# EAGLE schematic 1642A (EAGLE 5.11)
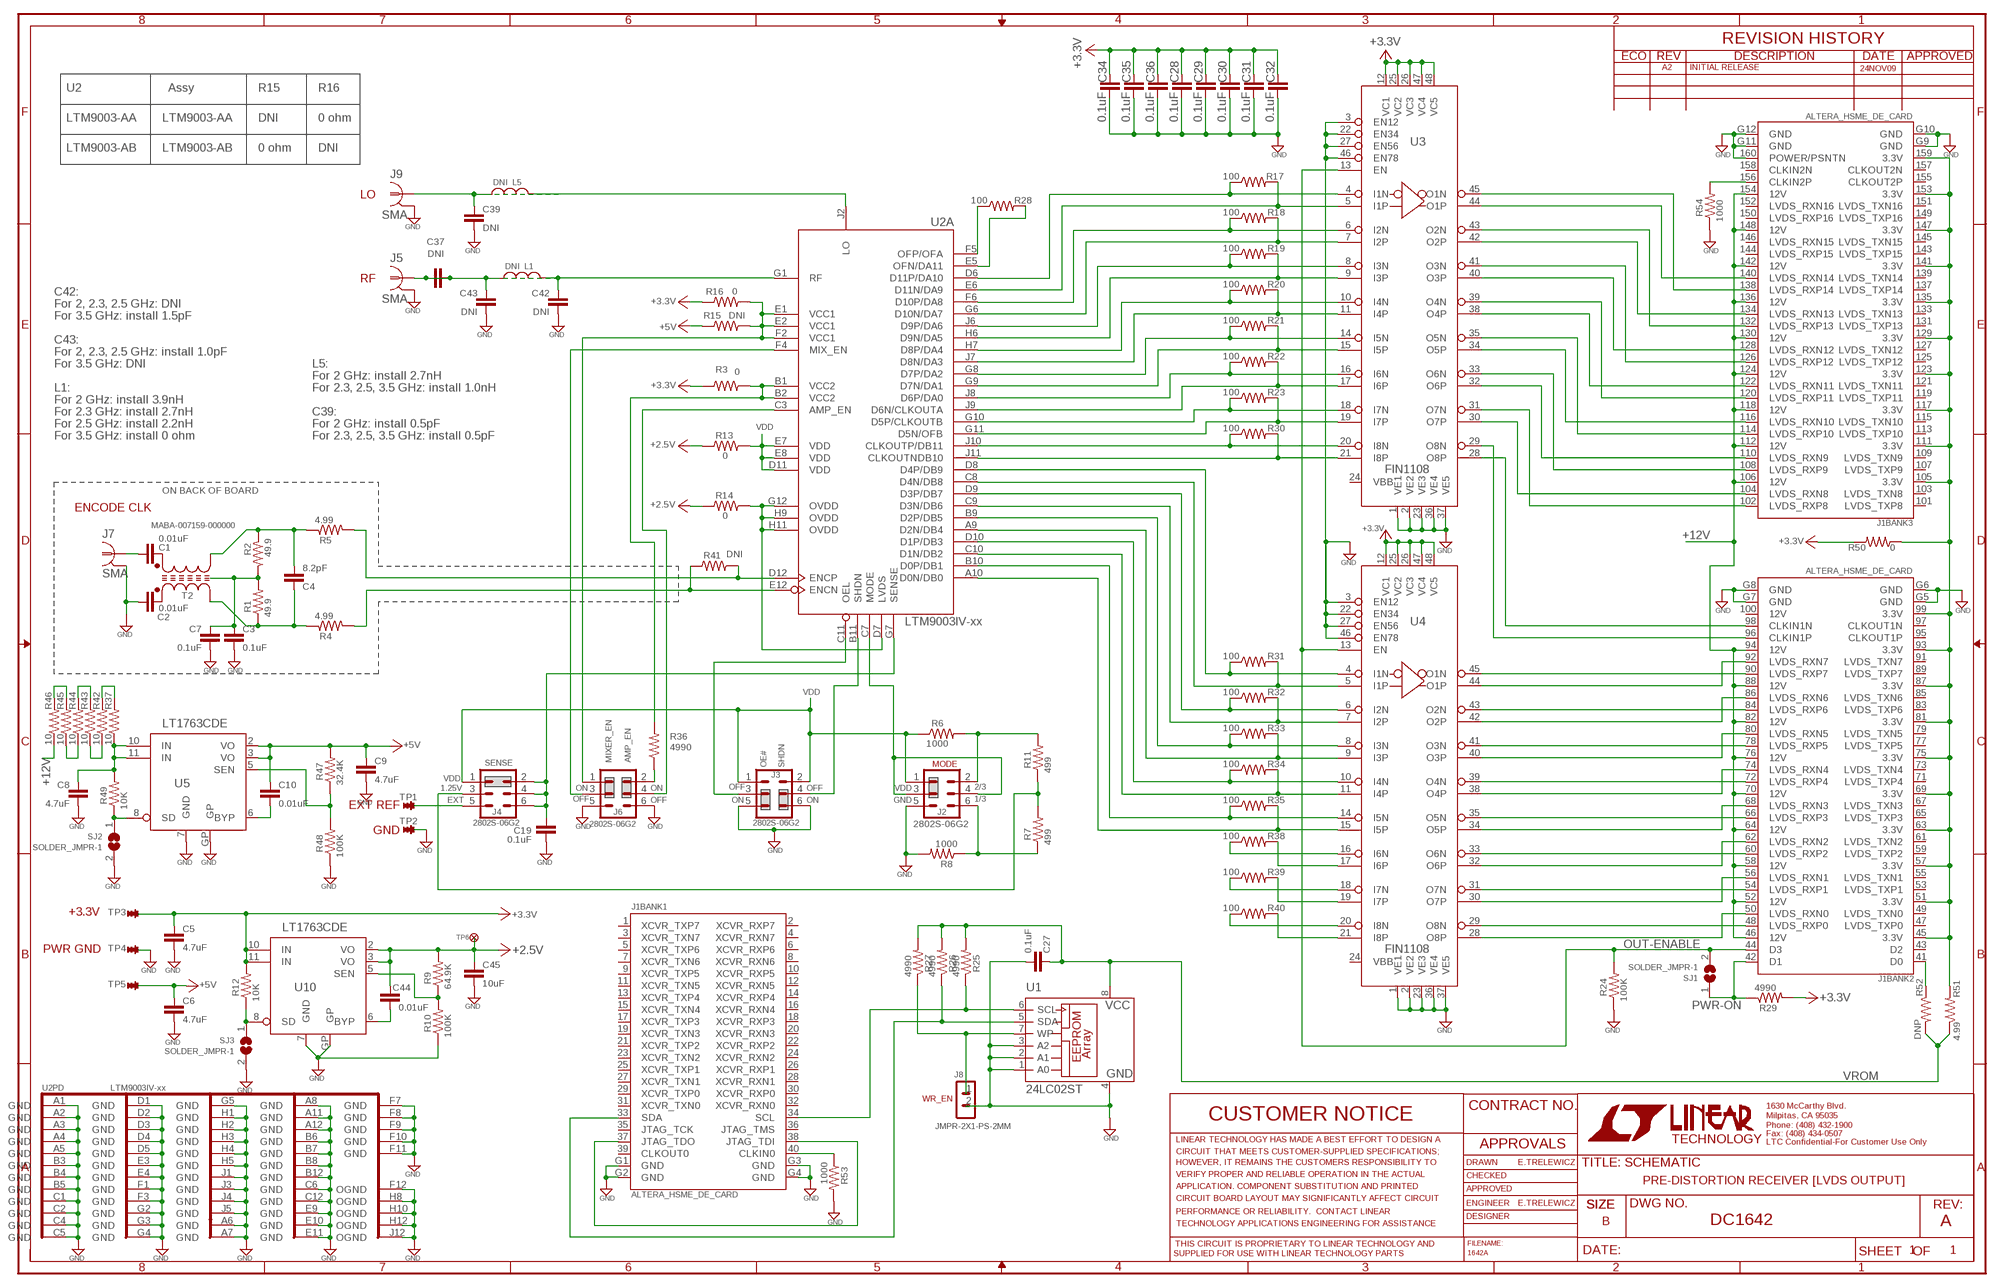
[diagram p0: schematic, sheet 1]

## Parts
C1  0.01uF  CAP-NP-SMT-C0402  [C0402]
C2  0.01uF  CAP-NP-SMT-C0402  [C0402]
C3  0.1uF  CAP-NP-SMT-C0603  [C0603]
C4  8.2pF  CAP-NP-SMT-C0402  [C0402]
C5  4.7uF  CAP-NP-SMT-C0805  [C0805]
C6  4.7uF  CAP-NP-SMT-C0805  [C0805]
C7  0.1uF  CAP-NP-SMT-C0603  [C0603]
C8  4.7uF  CAP-NP-SMT-C0805  [C0805]
C9  4.7uF  CAP-NP-SMT-C0805  [C0805]
C10  0.01uF  CAP-NP-SMT-C0402  [C0402]
C19  0.1uF  CAP-NP-SMT-C0402  [C0402]
C27  0.1uF  CAP-NP-SMT-C0402  [C0402]
C28  0.1uF  CAP-NP-SMT-C0402  [C0402]
C29  0.1uF  CAP-NP-SMT-C0402  [C0402]
C30  0.1uF  CAP-NP-SMT-C0402  [C0402]
C31  0.1uF  CAP-NP-SMT-C0402  [C0402]
C32  0.1uF  CAP-NP-SMT-C0402  [C0402]
C34  0.1uF  CAP-NP-SMT-C0402  [C0402]
C35  0.1uF  CAP-NP-SMT-C0402  [C0402]
C36  0.1uF  CAP-NP-SMT-C0402  [C0402]
C37  DNI  CAP-NP-SMT-C0402  [C0402]
C39  DNI  CAP-NP-SMT-C0402  [C0402]
C42  DNI  CAP-NP-SMT-C0402  [C0402]
C43  DNI  CAP-NP-SMT-C0402  [C0402]
C44  0.01uF  CAP-NP-SMT-C0402  [C0402]
C45  10uF  CAP-NP-SMT-C0805  [C0805]
J1  ALTERA_HSME_DE_CARD  [HSMC_ASP-122952-01_MEZZANINECARD]
J2  2802S-06G2  HDR-3X2-PS2MM  [HDR-3X2PS-2MM]
J3  2802S-06G2  HDR-3X2-PS2MM  [HDR-3X2PS-2MM]
J4  2802S-06G2  HDR-3X2-PS2MM  [HDR-3X2PS-2MM]
J5  SMA  RF_CONN-SMA-FEMALE-EDGE-MNT-GHZ  [SMA_FEMALE_EDGE_MNT_GHZ]
J6  2802S-06G2  HDR-3X2-PS2MM  [HDR-3X2PS-2MM]
J7  SMA  RF_CONN-SMA-FEMALE-EDGE-MNT  [SMA-FEMALE-EDGE-MNT]
J8  JMPR-2X1-PS-2MM  [HDR-2X1PS-2MM]
J9  SMA  RF_CONN-SMA-FEMALE-EDGE-MNT-GHZ  [SMA_FEMALE_EDGE_MNT_GHZ]
L1  DNI  IND-CER-SMT-0402  [L0402]
L5  DNI  IND-CER-SMT-0402  [L0402]
R1  49.9  RES-R0402  [R0402]
R2  49.9  RES-R0402  [R0402]
R3  0  RES-R0805  [R0805]
R4  4.99  RES-R0402  [R0402]
R5  4.99  RES-R0402  [R0402]
R6  1000  RES-R0603  [R0603]
R7  499  RES-R0603  [R0603]
R8  1000  RES-R0603  [R0603]
R9  64.9K  RES-R0402  [R0402]
R10  100K  RES-R0402  [R0402]
R11  499  RES-R0603  [R0603]
R12  10K  RES-R0402  [R0402]
R13  0  RES-R0805  [R0805]
R14  0  RES-R0805  [R0805]
R15  DNI  RES-R0805  [R0805]
R16  0  RES-R0805  [R0805]
R17  100  RES-R0201  [R0201]
R18  100  RES-R0201  [R0201]
R19  100  RES-R0201  [R0201]
R20  100  RES-R0201  [R0201]
R21  100  RES-R0201  [R0201]
R22  100  RES-R0201  [R0201]
R23  100  RES-R0201  [R0201]
R24  100K  RES-R0402  [R0402]
R25  4990  RES-R0402  [R0402]
R26  4990  RES-R0402  [R0402]
R27  4990  RES-R0402  [R0402]
R28  100  RES-R0201  [R0201]
R29  4990  RES-R0402  [R0402]
R30  100  RES-R0201  [R0201]
R31  100  RES-R0201  [R0201]
R32  100  RES-R0201  [R0201]
R33  100  RES-R0201  [R0201]
R34  100  RES-R0201  [R0201]
R35  100  RES-R0201  [R0201]
R36  4990  RES-R0402  [R0402]
R37  10  RES-R1206  [R1206]
R38  100  RES-R0201  [R0201]
R39  100  RES-R0201  [R0201]
R40  100  RES-R0201  [R0201]
R41  DNI  RES-R0201  [R0201]
R42  10  RES-R1206  [R1206]
R43  10  RES-R1206  [R1206]
R44  10  RES-R1206  [R1206]
R45  10  RES-R1206  [R1206]
R46  10  RES-R1206  [R1206]
R47  32.4K  RES-R0402  [R0402]
R48  100K  RES-R0402  [R0402]
R49  10K  RES-R0402  [R0402]
R50  0  RES-R1206  [R1206]
R51  4.99  RES-R0402  [R0402]
R52  DNP  RES-R0402  [R0402]
R53  1000  RES-R0603  [R0603]
R54  1000  RES-R0603  [R0603]
SJ1  SOLDER_JMPR-1  [SJ1]
SJ2  SOLDER_JMPR-1  [SJ1]
SJ3  SOLDER_JMPR-1  [SJ1]
T2  MABA-007159-000000  ETC1-1-13  [MACOM_ETC1-XFMR]
TP1  TURRET0.063  [TURRET_MILLMAX_2308-2]
TP2  TURRET0.063  [TURRET_MILLMAX_2308-2]
TP3  TURRET0.063  [TURRET_MILLMAX_2308-2]
TP4  TURRET0.063  [TURRET_MILLMAX_2308-2]
TP5  TURRET0.063  [TURRET_MILLMAX_2308-2]
TP6  TSTPNT25MIL  [VIA-25MIL]
U1  24LC02ST  [TSSOP8]
U2  LTM9003IV-xx  LTM9003  [LTM9003-RNDED]
U3  FIN1108  [TSSOP48]
U4  FIN1108  [TSSOP48]
U5  LT1763CDE  [DE12]
U10  LT1763CDE  [DE12]

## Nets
3.3VHOST: J1.45(BANK2:3.3V) J1.51(BANK2:3.3V) J1.57(BANK2:3.3V) J1.63(BANK2:3.3V) J1.69(BANK2:3.3V) J1.75(BANK2:3.3V) J1.81(BANK2:3.3V) J1.87(BANK2:3.3V) J1.93(BANK2:3.3V) J1.99(BANK2:3.3V) J1.105(BANK3:3.3V) J1.111(BANK3:3.3V) J1.117(BANK3:3.3V) J1.123(BANK3:3.3V) J1.129(BANK3:3.3V) J1.135(BANK3:3.3V) J1.141(BANK3:3.3V) J1.147(BANK3:3.3V) J1.153(BANK3:3.3V) J1.159(BANK3:3.3V) R50.1 R51.2
+2.5V: C44.1 C45.1 R9.2 R13.1 R14.1 TP6.1 U10.2(VO) U10.3(VO)
+3.3V: C5.1 C28.1 C29.1 C30.1 C31.1 C32.1 C34.1 C35.1 C36.1 R3.1 R12.2 R16.1 R29.2 R50.2 TP3.1 U3.12(VC1) U3.25(VC2) U3.26(VC3) U3.47(VC4) U3.48(VC5) U4.12(VC1) U4.25(VC2) U4.26(VC3) U4.47(VC4) U4.48(VC5) U10.10(IN) U10.11(IN)
+5V: C6.1 C9.1 C10.1 R15.1 R47.2 TP5.1 U5.2(VO) U5.3(VO)
+12V: J1.46(BANK2:12V) J1.52(BANK2:12V) J1.58(BANK2:12V) J1.64(BANK2:12V) J1.70(BANK2:12V) J1.76(BANK2:12V) J1.82(BANK2:12V) J1.88(BANK2:12V) J1.94(BANK2:12V) J1.106(BANK3:12V) J1.112(BANK3:12V) J1.118(BANK3:12V) J1.124(BANK3:12V) J1.130(BANK3:12V) J1.136(BANK3:12V) J1.142(BANK3:12V) J1.148(BANK3:12V) J1.154(BANK3:12V) R46.1
AMP_EN: J6.4 U2.C3(A:AMP_EN)
ECCN: R4.2 R41.1 U2.E12(A:ENCN)
ENCP: R5.2 R41.2 U2.D12(A:ENCP)
EXT_REF: J4.5 TP1.1
GND: C2.1 C3.2 C5.2 C6.2 C7.2 C8.2 C9.2 C19.2 C27.2 C28.2 C29.2 C30.2 C31.2 C32.2 C34.2 C35.2 C36.2 C39.2 C42.2 C43.2 C45.2 J1.160(BANK3:POWER/PSNTN) J1.G1(BANK1:GND) J1.G2(BANK1:GND) J1.G3(BANK1:GND) J1.G4(BANK1:GND) J1.G5(BANK2:GND) J1.G6(BANK2:GND) J1.G7(BANK2:GND) J1.G8(BANK2:GND) J1.G9(BANK3:GND) J1.G10(BANK3:GND) J1.G11(BANK3:GND) J1.G12(BANK3:GND) J2.5 J3.5 J3.6 J5.2(GND) J6.5 J6.6 J7.2(GND) J8.2 J9.2(GND) R8.2 R10.1 R24.1 R48.1 R53.2 R54.1 SJ2.2 SJ3.2 TP2.1 TP4.1 U1.1(A0) U1.2(A1) U1.3(A2) U1.4(GND) U2.A1(PD:GND) U2.A2(PD:GND) U2.A3(PD:GND) U2.A4(PD:GND) U2.A5(PD:GND) U2.A6(PD:GND) U2.A7(PD:GND) U2.A8(PD:GND) U2.A11(PD:GND) U2.A12(PD:GND) U2.B3(PD:GND) U2.B4(PD:GND) U2.B5(PD:GND) U2.B6(PD:GND) U2.B7(PD:GND) U2.B8(PD:GND) U2.B12(PD:GND) U2.C1(PD:GND) U2.C2(PD:GND) U2.C4(PD:GND) U2.C5(PD:GND) U2.C6(PD:GND) U2.C12(PD:GND) U2.D1(PD:GND) U2.D2(PD:GND) U2.D3(PD:GND) U2.D4(PD:GND) U2.D5(PD:GND) U2.E3(PD:GND) U2.E4(PD:GND) U2.E9(PD:GND) U2.E10(PD:GND) U2.E11(PD:GND) U2.F1(PD:GND) U2.F3(PD:GND) U2.F7(PD:GND) U2.F8(PD:GND) U2.F9(PD:GND) U2.F10(PD:GND) U2.F11(PD:GND) U2.F12(PD:OGND) U2.G2(PD:GND) U2.G3(PD:GND) U2.G4(PD:GND) U2.G5(PD:GND) U2.H1(PD:GND) U2.H2(PD:GND) U2.H3(PD:GND) U2.H4(PD:GND) U2.H5(PD:GND) U2.H8(PD:OGND) U2.H10(PD:OGND) U2.H12(PD:OGND) U2.J1(PD:GND) U2.J3(PD:GND) U2.J4(PD:GND) U2.J5(PD:GND) U2.J12(PD:OGND) U3.1(VE1) U3.2(VE2) U3.3(EN12) U3.22(EN34) U3.23(VE3) U3.27(EN56) U3.36(VE4) U3.37(VE5) U3.46(EN78) U4.1(VE1) U4.2(VE2) U4.3(EN12) U4.22(EN34) U4.23(VE3) U4.27(EN56) U4.36(VE4) U4.37(VE5) U4.46(EN78) U5.7(GND) U5.GP U10.7(GND) U10.GP
LO: L5.2 U2.J2(A:LO)
MIX_EN: J6.3 U2.F4(A:MIX_EN)
MODE: J2.3 J2.4 U2.C7(A:MODE)
N$1: C1.2 T2.4
N$2: C2.2 T2.5
N$3: C3.1 C7.1 R1.2 R2.2
N$4: C1.1 J7.1
N$5: R17.1 U2.D6(A:D11P/DA10) U3.4(I1N)
N$6: C4.2 R2.1 R5.1 T2.3
N$7: C4.1 R1.1 R4.1 T2.1
N$8: J6.2 R36.1
N$9: C37.1 C37.2 C43.1 J5.1 L1.1
N$10: R12.1 SJ3.1 U10.8(SD)
N$11: J2.6 R7.1 R8.1
N$12: R28.1 U2.F5(A:OFP/OFA)
N$13: C39.1 J9.1 L5.1
N$14: J1.48(BANK2:LVDS_RXP0) U4.29(O8N)
N$15: J2.2 R6.2 R11.2
N$16: J1.50(BANK2:LVDS_RXN0) U4.28(O8P)
N$17: J1.54(BANK2:LVDS_RXP1) U4.31(O7N)
N$18: J1.56(BANK2:LVDS_RXN1) U4.30(O7P)
N$19: J1.60(BANK2:LVDS_RXP2) U4.33(O6N)
N$20: J1.62(BANK2:LVDS_RXN2) U4.32(O6P)
N$21: J1.66(BANK2:LVDS_RXP3) U4.35(O5N)
N$22: J1.68(BANK2:LVDS_RXN3) U4.34(O5P)
N$23: J1.72(BANK2:LVDS_RXP4) U4.39(O4N)
N$24: J1.74(BANK2:LVDS_RXN4) U4.38(O4P)
N$25: J1.78(BANK2:LVDS_RXP5) U4.41(O3N)
N$26: J1.80(BANK2:LVDS_RXN5) U4.40(O3P)
N$27: J1.84(BANK2:LVDS_RXP6) U4.43(O2N)
N$28: J1.86(BANK2:LVDS_RXN6) U4.42(O2P)
N$29: J1.90(BANK2:LVDS_RXP7) U4.45(O1N)
N$30: R9.1 R10.2 U10.5(SEN)
N$31: J1.92(BANK2:LVDS_RXN7) U4.44(O1P)
N$32: J1.98(BANK2:CLKIN1N) U3.28(O8P)
N$33: J1.96(BANK2:CLKIN1P) U3.29(O8N)
N$34: J1.102(BANK3:LVDS_RXP8) U3.31(O7N)
N$35: J1.104(BANK3:LVDS_RXN8) U3.30(O7P)
N$36: C44.2 U10.6(BYP)
N$37: J1.108(BANK3:LVDS_RXP9) U3.33(O6N)
N$38: J1.110(BANK3:LVDS_RXN9) U3.32(O6P)
N$39: J1.114(BANK3:LVDS_RXP10) U3.35(O5N)
N$40: J1.116(BANK3:LVDS_RXN10) U3.34(O5P)
N$41: J1.120(BANK3:LVDS_RXP11) U3.39(O4N)
N$42: J1.122(BANK3:LVDS_RXN11) U3.38(O4P)
N$43: J1.126(BANK3:LVDS_RXP12) U3.41(O3N)
N$44: J1.128(BANK3:LVDS_RXN12) U3.40(O3P)
N$45: J1.132(BANK3:LVDS_RXP13) U3.43(O2N)
N$46: J1.134(BANK3:LVDS_RXN13) U3.42(O2P)
N$47: J1.41(BANK2:D0) R52.1
N$49: R28.2 U2.E5(A:OFN/DA11)
N$50: J1.138(BANK3:LVDS_RXP14) U3.45(O1N)
N$51: J1.140(BANK3:LVDS_RXN14) U3.44(O1P)
N$52: R49.1 SJ2.1 U5.8(SD)
N$53: R45.2 R46.2
N$54: R44.1 R45.1
N$55: R43.2 R44.2
N$56: J1.37(BANK1:JTAG_TDO) J1.38(BANK1:JTAG_TDI)
N$57: R42.1 R43.1
N$58: R37.2 R42.2
N$59: J1.40(BANK1:CLKIN0) R53.1
N$60: R30.2 U2.J11(A:CLKOUTNDB10) U3.21(I8P)
N$61: R47.1 R48.2 U5.5(SEN)
N$62: J1.156(BANK3:CLKIN2P) R54.2
N$63: R30.1 U2.J10(A:CLKOUTP/DB11) U3.20(I8N)
N$64: C10.2 U5.6(BYP)
N$65: R17.2 U2.E6(A:D11N/DA9) U3.5(I1P)
N$66: R18.1 U2.F6(A:D10P/DA8) U3.6(I2N)
N$68: R18.2 U2.G6(A:D10N/DA7) U3.7(I2P)
N$69: R34.1 U2.D10(A:D1P/DB3) U4.10(I4N)
N$70: R20.1 U2.H7(A:D8P/DA4) U3.10(I4N)
N$71: R35.1 U2.B10(A:D0P/DB1) U4.14(I5N)
N$73: R31.1 U2.D8(A:D4P/DB9) U4.4(I1N)
N$74: R21.1 U2.G8(A:D7P/DA2) U3.14(I5N)
N$75: R35.2 U2.A10(A:D0N/DB0) U4.15(I5P)
N$76: R22.1 U2.J8(A:D6P/DA0) U3.16(I6N)
N$77: R22.2 U2.J9(A:D6N/CLKOUTA) U3.17(I6P)
N$78: R23.1 U2.G10(A:D5P/CLKOUTB) U3.18(I7N)
N$81: R31.2 U2.C8(A:D4N/DB8) U4.5(I1P)
N$86: R39.2 U4.19(I7P)
N$88: R38.1 U4.16(I6N)
N$93: R23.2 U2.G11(A:D5N/OFB) U3.19(I7P)
N$95: R19.2 U2.H6(A:D9N/DA5) U3.9(I3P)
N$99: R20.2 U2.J7(A:D8N/DA3) U3.11(I4P)
N$100: R21.2 U2.G9(A:D7N/DA1) U3.15(I5P)
N$101: R19.1 U2.J6(A:D9P/DA6) U3.8(I3N)
N$105: R32.1 U2.D9(A:D3P/DB7) U4.6(I2N)
N$106: R32.2 U2.C9(A:D3N/DB6) U4.7(I2P)
N$107: R33.1 U2.B9(A:D2P/DB5) U4.8(I3N)
N$108: R33.2 U2.A9(A:D2N/DB4) U4.9(I3P)
N$109: R34.2 U2.C10(A:D1N/DB2) U4.11(I4P)
N$114: R38.2 U4.17(I6P)
N$124: R40.2 U4.21(I8P)
N$126: R39.1 U4.18(I7N)
N$131: R40.1 U4.20(I8N)
OEL: J3.3 U2.C11(A:OEL)
OUT-ENABLE: J1.44(BANK2:D3) R24.2 SJ1.2 U3.13(EN) U4.13(EN)
OVDD: R14.2 U2.D7(A:LVDS) U2.G12(A:OVDD) U2.H9(A:OVDD) U2.H11(A:OVDD)
PWR-ON: J1.42(BANK2:D1) R29.1 SJ1.1
RF: C42.1 L1.2 U2.G1(A:RF)
SCL: J1.34(BANK1:SCL) R25.1 U1.6(SCL)
SDA: J1.33(BANK1:SDA) R26.1 U1.5(SDA)
SENSE: C19.1 J4.2 J4.4 J4.6 U2.G7(A:SENSE)
SHDN: J3.4 U2.B11(A:SHDN)
VCC1: J6.1 R15.2 R16.2 U2.E1(A:VCC1) U2.E2(A:VCC1) U2.F2(A:VCC1)
VCC2: R3.2 R36.2 U2.B1(A:VCC2) U2.B2(A:VCC2)
VCM: J4.3 R7.2 R11.1
VDD: J2.1 J3.1 J3.2 J4.1 R6.1 R13.2 U2.D11(A:VDD) U2.E7(A:VDD) U2.E8(A:VDD)
VIN: C8.1 R37.1 R49.2 U5.10(IN) U5.11(IN)
VROM: C27.1 R25.2 R26.2 R27.2 R51.1 R52.2 U1.8(VCC)
WP: J8.1 R27.1 U1.7(WP)
Unconnected: J1.1(BANK1:XCVR_TXP7) J1.2(BANK1:XCVR_RXP7) J1.3(BANK1:XCVR_TXN7) J1.4(BANK1:XCVR_RXN7) J1.5(BANK1:XCVR_TXP6) J1.6(BANK1:XCVR_RXP6) J1.7(BANK1:XCVR_TXN6) J1.8(BANK1:XCVR_RXN6) J1.9(BANK1:XCVR_TXP5) J1.10(BANK1:XCVR_RXP5) J1.11(BANK1:XCVR_TXN5) J1.12(BANK1:XCVR_RXN5) J1.13(BANK1:XCVR_TXP4) J1.14(BANK1:XCVR_RXP4) J1.15(BANK1:XCVR_TXN4) J1.16(BANK1:XCVR_RXN4) J1.17(BANK1:XCVR_TXP3) J1.18(BANK1:XCVR_RXP3) J1.19(BANK1:XCVR_TXN3) J1.20(BANK1:XCVR_RXN3) J1.21(BANK1:XCVR_TXP2) J1.22(BANK1:XCVR_RXP2) J1.23(BANK1:XCVR_TXN2) J1.24(BANK1:XCVR_RXN2) J1.25(BANK1:XCVR_TXP1) J1.26(BANK1:XCVR_RXP1) J1.27(BANK1:XCVR_TXN1) J1.28(BANK1:XCVR_RXN1) J1.29(BANK1:XCVR_TXP0) J1.30(BANK1:XCVR_RXP0) J1.31(BANK1:XCVR_TXN0) J1.32(BANK1:XCVR_RXN0) J1.35(BANK1:JTAG_TCK) J1.36(BANK1:JTAG_TMS) J1.39(BANK1:CLKOUT0) J1.43(BANK2:D2) J1.47(BANK2:LVDS_TXP0) J1.49(BANK2:LVDS_TXN0) J1.53(BANK2:LVDS_TXP1) J1.55(BANK2:LVDS_TXN1) J1.59(BANK2:LVDS_TXP2) J1.61(BANK2:LVDS_TXN2) J1.65(BANK2:LVDS_TXP3) J1.67(BANK2:LVDS_TXN3) J1.71(BANK2:LVDS_TXP4) J1.73(BANK2:LVDS_TXN4) J1.77(BANK2:LVDS_TXP5) J1.79(BANK2:LVDS_TXN5) J1.83(BANK2:LVDS_TXP6) J1.85(BANK2:LVDS_TXN6) J1.89(BANK2:LVDS_TXP7) J1.91(BANK2:LVDS_TXN7) J1.95(BANK2:CLKOUT1P) J1.97(BANK2:CLKOUT1N) J1.100(BANK2:12V) J1.101(BANK3:LVDS_TXP8) J1.103(BANK3:LVDS_TXN8) J1.107(BANK3:LVDS_TXP9) J1.109(BANK3:LVDS_TXN9) J1.113(BANK3:LVDS_TXP10) J1.115(BANK3:LVDS_TXN10) J1.119(BANK3:LVDS_TXP11) J1.121(BANK3:LVDS_TXN11) J1.125(BANK3:LVDS_TXP12) J1.127(BANK3:LVDS_TXN12) J1.131(BANK3:LVDS_TXP13) J1.133(BANK3:LVDS_TXN13) J1.137(BANK3:LVDS_TXP14) J1.139(BANK3:LVDS_TXN14) J1.143(BANK3:LVDS_TXP15) J1.144(BANK3:LVDS_RXP15) J1.145(BANK3:LVDS_TXN15) J1.146(BANK3:LVDS_RXN15) J1.149(BANK3:LVDS_TXP16) J1.150(BANK3:LVDS_RXP16) J1.151(BANK3:LVDS_TXN16) J1.152(BANK3:LVDS_RXN16) J1.155(BANK3:CLKOUT2P) J1.157(BANK3:CLKOUT2N) J1.158(BANK3:CLKIN2N) U3.24(VBB) U4.24(VBB)

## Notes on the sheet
- A2 | INITIAL RELEASE | 24NOV09
- U2 | Assy | R15 | R16
- LTM9003-AA | LTM9003-AA | DNI | 0 ohm
- LTM9003-AB | LTM9003-AB | 0 ohm | DNI
- LO
- RF
- C42:
- For 2, 2.3, 2.5 GHz: DNI
- For 3.5 GHz: install 1.5pF
- C43:
- For 2, 2.3, 2.5 GHz: install 1.0pF
- For 3.5 GHz: DNI | L5:
- For 2 GHz: install 2.7nH
- L1: | For 2.3, 2.5, 3.5 GHz: install 1.0nH
- For 2 GHz: install 3.9nH
- For 2.3 GHz: install 2.7nH | C39:
- For 2.5 GHz: install 2.2nH | For 2 GHz: install 0.5pF
- For 3.5 GHz: install 0 ohm | For 2.3, 2.5, 3.5 GHz: install 0.5pF
- ON BACK OF BOARD
- ENCODE CLK
- MIXER_EN | AMP_EN
- SENSE | OE# | SHDN | MODE
- VDD
- 1.25V | ON | ON | OFF | OFF | VDD | 2/3
- EXT | OFF | OFF | ON | ON | GND | 1/3
- EXT REF
- GND
- +3.3V
- PWR GND
- WR_EN
- E.TRELEWICZ
- PRE-DISTORTION RECEIVER [LVDS OUTPUT]
- E.TRELEWICZ
- B | DC1642 | A
- 1 | 1

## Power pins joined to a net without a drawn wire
GND: J5.3(GND) J5.4(GND) J5.5(GND) J7.3(GND) J7.4(GND) J7.5(GND) J9.3(GND) J9.4(GND) J9.5(GND)

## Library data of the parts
C1-C10 C19 C27-C32 C34-C37 C39 C42-C45 = LTDB_Passives:CAP-NP-SMT-: Capacitor; Non-polar; SMT
J1 = LTDB_Connectors:ALTERA_HSME_DE_?: Altera HSMS Differential Signals
J2-J4 J6 = LTDB_Connectors:HDR-3X2-PS: Header 3x2 Pin, Straight
J5 J7 J9 = LTDB_Connectors:RF_CONN-: BNC CONNECTOR M/A COM www.macom.com distributor Farnell 149-452
J8 = LTDB_Connectors:JMPR-2X1-PS?: Header, 2x1, 2mm
L1 L5 = LTDB_Passives:IND-CER-SMT-: Inductor,Ceramic,SMT
R1-R54 = LTDB_Passives:RES-: Resistor; GP
SJ1-SJ3 = LTDB_Connectors:SOLDER_JMPR-1
T2 = LTDB_Passives:ETC1-1-13: Balun 1:1, SMT, MaCom
TP1-TP5 = LTDB_Connectors:TURRET: Turret
TP6 = LTDB_Connectors:TSTPNT?
U1 = LTDB_ICs:24*?: I2C SEEP Memory
U2 = LTDB_Linear_Parts:LTM9003: Pre-distortion Receiver Module
U3 U4 = LTDB_ICs:FIN1108*: REPEATER,OCTAL,LVDS
U5 U10 = LTDB_Linear_Parts:LT1763CDE: LDO, SMT, DFN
